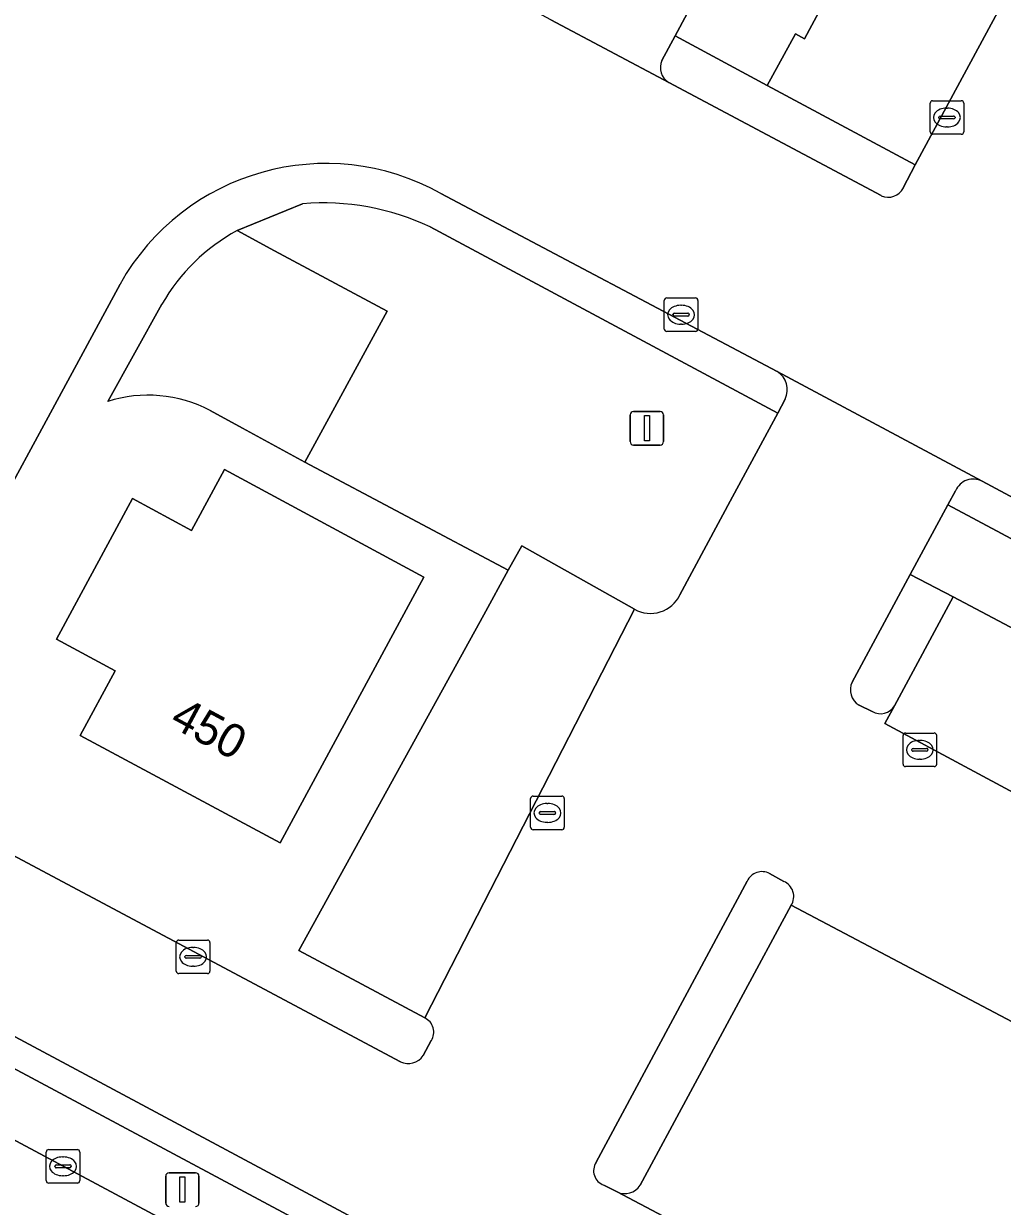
# Model space of a CAD drawing. Extents: x 159489 to 160304, y 383825 to 384531.
# Drawn here: x 159850 to 159879.12, y 383987.85 to 384023.04 of the extents above; entities that cross this region are included whole.
import ezdxf

# ---------------------------------------------------------------- set-up
doc = ezdxf.new("R2010")
doc.units = 0
for name, color, linetype in [('IMGEO_Fietspad_gesloten', 7, 'Continuous'), ('IMGEO_Groenvoorziening', 7, 'Continuous'), ('IMGEO_Haag', 7, 'Continuous'), ('IMGEO_Kolk', 7, 'Continuous'), ('IMGEO_Lichtmast', 7, 'Continuous'), ('IMGEO_Pand', 7, 'Continuous'), ('IMGEO_Pand_nummerreeks', 7, 'Continuous'), ('IMGEO_Parkeervlak_open', 7, 'Continuous'), ('IMGEO_Rijbaan_lokaal_open', 7, 'Continuous'), ('IMGEO_Verkeerseiland_open', 7, 'Continuous'), ('IMGEO_Voetpad_open', 7, 'Continuous')]:
    doc.layers.add(name, color=color, linetype=linetype)

msp = doc.modelspace()

# ---------------------------------------------------------------- linework, layer by layer
at = {"layer": 'IMGEO_Fietspad_gesloten'}
msp.add_lwpolyline([(159914.789, 383954.987), (159829.267, 384000.762), (159827.511, 384001.747), (159820.478, 384006.14), (159815.453, 384008.909), (159814.236, 384009.579), (159812.526, 384010.519), (159810.974, 384011.376), (159809.37, 384007.908)], dxfattribs=at)
at = {"layer": 'IMGEO_Groenvoorziening'}
for points in [[(159874.457, 384024.881), (159874.193, 384025.023), (159893.364, 384060.587), (159890.554, 384062.073), (159888.442, 384058.08), (159889.973, 384057.263), (159884.958, 384047.928), (159883.393, 384048.779), (159869.376, 384022.671), (159872.12, 384021.198), (159872.962, 384022.731), (159873.226, 384022.589)], [(159877.493, 384008.721), (159876.374, 384006.647), (159877.656, 384005.98), (159909.675, 383989.022), (159910.523, 383990.514), (159910.77, 383990.949)]]:
    msp.add_lwpolyline(points, close=True, dxfattribs=at)
for points in [[(159876.169, 384018.149), (159876.524, 384018.834), (159872.12, 384021.198), (159869.376, 384022.671), (159868.985, 384021.943)], [(159869.191, 384021.286), (159875.512, 384017.919)], [(159858.296, 384017.677), (159856.348, 384016.881), (159857.464, 384016.281), (159860.815, 384014.481), (159858.359, 384009.988), (159864.415, 384006.774), (159864.817, 384007.504), (159865.452, 384007.146), (159868.17, 384005.614)], [(159869.523, 384006.042), (159871.091, 384008.959), (159872.432, 384011.452), (159862.09, 384016.991)], [(159833.623, 384000.986), (159833.449, 384000.644), (159914.348, 383957.355), (159917.967, 383963.931), (159926.977, 383980.784), (159923.758, 383982.469), (159924.418, 383983.659), (159923.163, 383984.322), (159922.762, 383983.587), (159923.422, 383983.268), (159922.699, 383982), (159926.104, 383980.377), (159914.162, 383958.38), (159910.232, 383960.503), (159906.502, 383962.5), (159847.363, 383994.162), (159843.388, 383996.29), (159837.377, 383999.508), (159836.092, 384000.196)]]:
    msp.add_lwpolyline(points, dxfattribs=at)
for centre, radius, start, end in [((159869.457, 384021.73), 0.518, 155.7165, 239.1007), ((159875.721, 384018.376), 0.503, 245.4836, 333.1042), ((159858.904, 384010.204), 7.498, 64.8529, 94.649), ((159868.645, 384006.466), 0.975, 240.8553, 334.2526)]:
    msp.add_arc(centre, radius, start, end, dxfattribs=at)
at = {"layer": 'IMGEO_Haag'}
for points in [[(159876.169, 384018.149), (159876.524, 384018.834), (159872.12, 384021.198), (159869.376, 384022.671), (159868.985, 384021.943)], [(159869.191, 384021.286), (159875.512, 384017.919)]]:
    msp.add_lwpolyline(points, dxfattribs=at)
for centre, radius, start, end in [((159869.457, 384021.73), 0.518, 155.7165, 239.1007), ((159875.721, 384018.376), 0.503, 245.4836, 333.1042)]:
    msp.add_arc(centre, radius, start, end, dxfattribs=at)
at = {"layer": 'IMGEO_Kolk'}
for p, q in [((159876.966, 384019.818), (159876.966, 384020.67)), ((159877.041, 384020.744), (159877.893, 384020.744)), ((159877.967, 384020.67), (159877.967, 384019.818)), ((159877.454, 384020.524), (159877.479, 384020.524)), ((159877.225, 384020.238), (159877.225, 384020.25)), ((159877.663, 384020.201), (159877.265, 384020.201)), ((159877.268, 384020.287), (159877.666, 384020.287)), ((159877.477, 384019.964), (159877.452, 384019.964)), ((159877.709, 384020.25), (159877.709, 384020.238)), ((159877.893, 384019.744), (159877.041, 384019.744)), ((159869.057, 384013.951), (159869.057, 384014.803)), ((159869.132, 384014.877), (159869.984, 384014.877)), ((159870.058, 384014.803), (159870.058, 384013.951)), ((159869.316, 384014.371), (159869.316, 384014.383)), ((159869.754, 384014.334), (159869.356, 384014.334)), ((159869.359, 384014.42), (159869.757, 384014.42)), ((159869.545, 384014.657), (159869.57, 384014.657)), ((159869.8, 384014.383), (159869.8, 384014.371)), ((159869.568, 384014.097), (159869.543, 384014.097)), ((159869.984, 384013.877), (159869.132, 384013.877)), ((159876.16, 384001.006), (159876.16, 384001.858)), ((159876.235, 384001.932), (159877.087, 384001.932)), ((159876.648, 384001.712), (159876.673, 384001.712)), ((159877.161, 384001.858), (159877.161, 384001.006)), ((159876.419, 384001.426), (159876.419, 384001.438)), ((159876.857, 384001.389), (159876.459, 384001.389)), ((159876.462, 384001.475), (159876.86, 384001.475)), ((159876.903, 384001.438), (159876.903, 384001.426)), ((159876.671, 384001.152), (159876.646, 384001.152)), ((159877.087, 384000.932), (159876.235, 384000.932)), ((159865.079, 383999.128), (159865.079, 383999.98)), ((159865.154, 384000.054), (159866.006, 384000.054)), ((159866.08, 383999.98), (159866.08, 383999.128)), ((159865.338, 383999.548), (159865.338, 383999.56)), ((159865.381, 383999.597), (159865.779, 383999.597)), ((159865.567, 383999.834), (159865.592, 383999.834)), ((159865.822, 383999.56), (159865.822, 383999.548)), ((159865.776, 383999.511), (159865.378, 383999.511)), ((159865.59, 383999.274), (159865.565, 383999.274)), ((159866.006, 383999.054), (159865.154, 383999.054)), ((159854.537, 383994.847), (159854.537, 383995.699)), ((159854.612, 383995.773), (159855.464, 383995.773)), ((159855.538, 383995.699), (159855.538, 383994.847)), ((159855.025, 383995.553), (159855.05, 383995.553)), ((159854.796, 383995.267), (159854.796, 383995.279)), ((159855.234, 383995.23), (159854.836, 383995.23)), ((159854.839, 383995.316), (159855.237, 383995.316)), ((159855.048, 383994.993), (159855.023, 383994.993)), ((159855.28, 383995.279), (159855.28, 383995.267)), ((159855.464, 383994.773), (159854.612, 383994.773)), ((159850.667, 383988.614), (159850.667, 383989.466)), ((159850.742, 383989.54), (159851.594, 383989.54)), ((159851.668, 383989.466), (159851.668, 383988.614)), ((159850.926, 383989.034), (159850.926, 383989.046)), ((159850.969, 383989.083), (159851.367, 383989.083)), ((159851.155, 383989.32), (159851.18, 383989.32)), ((159851.41, 383989.046), (159851.41, 383989.034)), ((159851.364, 383988.997), (159850.966, 383988.997)), ((159851.178, 383988.76), (159851.153, 383988.76)), ((159851.594, 383988.54), (159850.742, 383988.54))]:
    msp.add_line(p, q, dxfattribs=at)
for points in [[(159876.966, 384019.818), (159876.966, 384020.67)], [(159877.041, 384020.744), (159877.893, 384020.744)], [(159877.967, 384020.67), (159877.967, 384019.818)], [(159877.893, 384019.744), (159877.041, 384019.744)], [(159869.057, 384013.951), (159869.057, 384014.803)], [(159869.132, 384014.877), (159869.984, 384014.877)], [(159870.058, 384014.803), (159870.058, 384013.951)], [(159869.984, 384013.877), (159869.132, 384013.877)], [(159876.16, 384001.006), (159876.16, 384001.858)], [(159876.235, 384001.932), (159877.087, 384001.932)], [(159877.161, 384001.858), (159877.161, 384001.006)], [(159877.087, 384000.932), (159876.235, 384000.932)], [(159865.079, 383999.128), (159865.079, 383999.98)], [(159865.154, 384000.054), (159866.006, 384000.054)], [(159866.08, 383999.98), (159866.08, 383999.128)], [(159866.006, 383999.054), (159865.154, 383999.054)], [(159854.537, 383994.847), (159854.537, 383995.699)], [(159854.612, 383995.773), (159855.464, 383995.773)], [(159855.538, 383995.699), (159855.538, 383994.847)], [(159855.464, 383994.773), (159854.612, 383994.773)], [(159850.667, 383988.614), (159850.667, 383989.466)], [(159850.742, 383989.54), (159851.594, 383989.54)], [(159851.668, 383989.466), (159851.668, 383988.614)], [(159851.594, 383988.54), (159850.742, 383988.54)]]:
    msp.add_lwpolyline(points, dxfattribs=at)
for centre, radius, start, end in [((159877.043, 384020.668), 0.0765, 91.552, 178.448), ((159877.043, 384020.668), 0.0765, 91.552, 178.448), ((159877.891, 384020.668), 0.0765, 1.552, 88.448), ((159877.891, 384020.668), 0.0765, 1.552, 88.448), ((159877.265, 384020.247), 0.0403, 85.8775, 175.7526), ((159877.262, 384020.237), 0.0366, 178.938, 274.7102), ((159877.666, 384020.244), 0.043, 264.8664, 352.4533), ((159877.67, 384020.249), 0.0386, 1.7309, 96.639), ((159877.043, 384019.82), 0.0765, 181.552, 268.448), ((159877.043, 384019.82), 0.0765, 181.552, 268.448), ((159877.891, 384019.82), 0.0765, 271.552, 358.448), ((159877.891, 384019.82), 0.0765, 271.552, 358.448), ((159869.134, 384014.801), 0.0765, 91.552, 178.448), ((159869.134, 384014.801), 0.0765, 91.552, 178.448), ((159869.982, 384014.801), 0.0765, 1.552, 88.448), ((159869.982, 384014.801), 0.0765, 1.552, 88.448), ((159869.356, 384014.38), 0.0403, 85.8775, 175.7526), ((159869.353, 384014.37), 0.0366, 178.938, 274.7102), ((159869.757, 384014.377), 0.043, 264.8664, 352.4533), ((159869.761, 384014.382), 0.0386, 1.7309, 96.639), ((159869.134, 384013.953), 0.0765, 181.552, 268.448), ((159869.134, 384013.953), 0.0765, 181.552, 268.448), ((159869.982, 384013.953), 0.0765, 271.552, 358.448), ((159869.982, 384013.953), 0.0765, 271.552, 358.448), ((159876.237, 384001.856), 0.0765, 91.552, 178.448), ((159876.237, 384001.856), 0.0765, 91.552, 178.448), ((159877.085, 384001.856), 0.0765, 1.552, 88.448), ((159877.085, 384001.856), 0.0765, 1.552, 88.448), ((159876.459, 384001.435), 0.0403, 85.8775, 175.7526), ((159876.456, 384001.425), 0.0366, 178.938, 274.7102), ((159876.86, 384001.432), 0.043, 264.8664, 352.4533), ((159876.864, 384001.437), 0.0386, 1.7309, 96.639), ((159876.237, 384001.008), 0.0765, 181.552, 268.448), ((159876.237, 384001.008), 0.0765, 181.552, 268.448), ((159877.085, 384001.008), 0.0765, 271.552, 358.448), ((159877.085, 384001.008), 0.0765, 271.552, 358.448), ((159865.156, 383999.978), 0.0765, 91.552, 178.448), ((159865.156, 383999.978), 0.0765, 91.552, 178.448), ((159866.004, 383999.978), 0.0765, 1.552, 88.448), ((159866.004, 383999.978), 0.0765, 1.552, 88.448), ((159865.378, 383999.557), 0.0403, 85.8775, 175.7526), ((159865.783, 383999.559), 0.0386, 1.7309, 96.639), ((159865.375, 383999.547), 0.0366, 178.938, 274.7102), ((159865.779, 383999.554), 0.043, 264.8664, 352.4533), ((159865.156, 383999.13), 0.0765, 181.552, 268.448), ((159865.156, 383999.13), 0.0765, 181.552, 268.448), ((159866.004, 383999.13), 0.0765, 271.552, 358.448), ((159866.004, 383999.13), 0.0765, 271.552, 358.448), ((159854.614, 383995.697), 0.0765, 91.552, 178.448), ((159854.614, 383995.697), 0.0765, 91.552, 178.448), ((159855.462, 383995.697), 0.0765, 1.552, 88.448), ((159855.462, 383995.697), 0.0765, 1.552, 88.448), ((159854.836, 383995.276), 0.0403, 85.8775, 175.7526), ((159854.833, 383995.266), 0.0366, 178.938, 274.7102), ((159855.237, 383995.273), 0.043, 264.8664, 352.4533), ((159855.241, 383995.278), 0.0386, 1.7309, 96.639), ((159854.614, 383994.849), 0.0765, 181.552, 268.448), ((159854.614, 383994.849), 0.0765, 181.552, 268.448), ((159855.462, 383994.849), 0.0765, 271.552, 358.448), ((159855.462, 383994.849), 0.0765, 271.552, 358.448), ((159850.744, 383989.464), 0.0765, 91.552, 178.448), ((159850.744, 383989.464), 0.0765, 91.552, 178.448), ((159851.592, 383989.464), 0.0765, 1.552, 88.448), ((159851.592, 383989.464), 0.0765, 1.552, 88.448), ((159850.966, 383989.043), 0.0403, 85.8775, 175.7526), ((159850.963, 383989.033), 0.0366, 178.938, 274.7102), ((159851.367, 383989.04), 0.043, 264.8664, 352.4533), ((159851.371, 383989.045), 0.0386, 1.7309, 96.639), ((159850.744, 383988.616), 0.0765, 181.552, 268.448), ((159850.744, 383988.616), 0.0765, 181.552, 268.448), ((159851.592, 383988.616), 0.0765, 271.552, 358.448), ((159851.592, 383988.616), 0.0765, 271.552, 358.448)]:
    msp.add_arc(centre, radius, start, end, dxfattribs=at)
for centre, major_axis, ratio, start_param, end_param in [((159877.453, 384020.244), (-0.387, 0.002), 0.722429, 4.712389, 7.853982), ((159877.478, 384020.244), (-0.39, 0.002), 0.717154, 1.570796, 4.712389), ((159869.544, 384014.377), (-0.387, 0.002), 0.722429, 4.712389, 7.853982), ((159869.569, 384014.377), (-0.39, 0.002), 0.717154, 1.570796, 4.712389), ((159876.647, 384001.432), (-0.387, 0.002), 0.722429, 4.712389, 7.853982), ((159876.672, 384001.432), (-0.39, 0.002), 0.717154, 1.570796, 4.712389), ((159865.566, 383999.554), (-0.387, 0.002), 0.722429, 4.712389, 7.853982), ((159865.591, 383999.554), (-0.39, 0.002), 0.717154, 1.570796, 4.712389), ((159855.024, 383995.273), (-0.387, 0.002), 0.722429, 4.712389, 7.853982), ((159855.049, 383995.273), (-0.39, 0.002), 0.717154, 1.570796, 4.712389), ((159851.154, 383989.04), (-0.387, 0.002), 0.722429, 4.712389, 7.853982), ((159851.179, 383989.04), (-0.39, 0.002), 0.717154, 1.570796, 4.712389)]:
    msp.add_ellipse(centre, major_axis=major_axis, ratio=ratio, start_param=start_param, end_param=end_param, dxfattribs=at)
at = {"layer": 'IMGEO_Lichtmast'}
for p, q in [((159868.044, 384010.6), (159868.044, 384011.4)), ((159868.044, 384011.4), (159868.044, 384010.6)), ((159868.144, 384011.5), (159868.934, 384011.5)), ((159868.934, 384011.5), (159868.144, 384011.5)), ((159869.034, 384011.4), (159869.034, 384010.6)), ((159869.034, 384010.6), (159869.034, 384011.4)), ((159868.934, 384010.5), (159868.144, 384010.5)), ((159868.144, 384010.5), (159868.934, 384010.5)), ((159854.223, 383987.949), (159854.223, 383988.749)), ((159854.223, 383988.749), (159854.223, 383987.949)), ((159854.323, 383988.849), (159855.113, 383988.849)), ((159855.113, 383988.849), (159854.323, 383988.849)), ((159855.213, 383988.749), (159855.213, 383987.949)), ((159855.213, 383987.949), (159855.213, 383988.749))]:
    msp.add_line(p, q, dxfattribs=at)
for points in [[(159868.464, 384011.375), (159868.614, 384011.375), (159868.614, 384010.625), (159868.464, 384010.625), (159868.464, 384011.375)], [(159854.643, 383988.724), (159854.793, 383988.724), (159854.793, 383987.974), (159854.643, 383987.974), (159854.643, 383988.724)]]:
    msp.add_lwpolyline(points, dxfattribs=at)
for centre, start, end in [((159868.144, 384011.4), 90, 180), ((159868.144, 384011.4), 90, 180), ((159868.934, 384011.4), 0, 90), ((159868.934, 384011.4), 360, 90), ((159868.144, 384010.6), 180, 270), ((159868.144, 384010.6), 180, 270), ((159868.934, 384010.6), 270, 0), ((159868.934, 384010.6), 270, 0), ((159854.323, 383988.749), 90, 180), ((159854.323, 383988.749), 90, 180), ((159855.113, 383988.749), 0, 90), ((159855.113, 383988.749), 360, 90), ((159854.323, 383987.949), 180, 270), ((159854.323, 383987.949), 180, 270), ((159855.113, 383987.949), 270, 0), ((159855.113, 383987.949), 270, 0)]:
    msp.add_arc(centre, 0.1, start, end, dxfattribs=at)
at = {"layer": 'IMGEO_Pand'}
msp.add_lwpolyline([(159861.9, 384006.569), (159855.968, 384009.769), (159854.991, 384007.958), (159853.233, 384008.905), (159850.977, 384004.724), (159852.72, 384003.785), (159851.682, 384001.859), (159857.633, 383998.662)], close=True, dxfattribs=at)
at = {"layer": 'IMGEO_Parkeervlak_open'}
for points in [[(159874.193, 384025.023), (159874.457, 384024.881), (159873.226, 384022.589), (159872.962, 384022.731), (159872.12, 384021.198), (159876.524, 384018.834), (159897.776, 384058.178), (159893.364, 384060.587)], [(159863.687, 384005.452), (159858.186, 383995.461), (159861.931, 383993.454), (159868.17, 384005.614), (159865.452, 384007.146), (159864.817, 384007.504), (159864.415, 384006.774)]]:
    msp.add_lwpolyline(points, close=True, dxfattribs=at)
for points in [[(159877.656, 384005.98), (159875.904, 384002.74), (159875.621, 384002.213), (159919.935, 383978.4), (159921.133, 383980.608), (159914.053, 383984.387)], [(159913.858, 383985.002), (159914.597, 383986.412), (159914.755, 383986.344), (159915.401, 383987.574), (159915.762, 383988.26), (159914.924, 383988.73), (159914.706, 383988.28), (159913.969, 383986.762), (159909.675, 383989.022), (159877.656, 384005.98)], [(159901.88, 383970.695), (159903.894, 383974.382), (159906.443, 383979.069), (159872.835, 383996.806), (159868.337, 383988.475)], [(159867.655, 383988.277), (159902.095, 383970.059)]]:
    msp.add_lwpolyline(points, dxfattribs=at)
msp.add_arc((159867.88, 383988.774), 0.546, 245.5973, 326.7811, dxfattribs=at)
at = {"layer": 'IMGEO_Rijbaan_lokaal_open'}
for points in [[(159875.512, 384017.919), (159869.191, 384021.286), (159865.68, 384023.154), (159860.405, 384026.005), (159861.02, 384027.132), (159860.011, 384027.627), (159880.733, 384067.348), (159880.944, 384067.749)], [(159897.994, 384058.567), (159897.776, 384058.178), (159876.524, 384018.834), (159876.169, 384018.149)], [(159862.412, 384017.983), (159872.417, 384012.684), (159878.518, 384009.42), (159910.32, 383992.364), (159917.028, 383988.832), (159927.536, 383983.189)], [(159847.152, 384004.753), (159852.866, 384015.29)], [(159878.518, 384009.42), (159872.417, 384012.684)], [(159872.655, 384011.867), (159872.432, 384011.452), (159871.091, 384008.959), (159869.523, 384006.042)], [(159874.648, 384003.449), (159876.374, 384006.647), (159877.493, 384008.721), (159877.72, 384009.141)], [(159868.17, 384005.614), (159861.931, 383993.454)], [(159861.206, 383992.151), (159849.659, 383998.303), (159847.363, 383994.162), (159906.502, 383962.5), (159910.232, 383960.503), (159914.616, 383968.515), (159917.813, 383973.681), (159920.243, 383978.197), (159919.935, 383978.4), (159875.621, 384002.213), (159875.904, 384002.74)], [(159875.247, 384002.57), (159874.853, 384002.762)], [(159867.028, 383989.16), (159871.521, 383997.524)], [(159872.192, 383997.754), (159872.613, 383997.519)], [(159872.835, 383996.806), (159906.443, 383979.069)], [(159862.126, 383992.78), (159861.885, 383992.333)], [(159902.664, 383969.778), (159902.095, 383970.059), (159867.655, 383988.277), (159867.258, 383988.481)]]:
    msp.add_lwpolyline(points, dxfattribs=at)
for centre, radius, start, end in [((159858.989, 384011.852), 7.022, 60.8254, 150.683), ((159875.721, 384018.376), 0.503, 245.4836, 333.1042), ((159872.083, 384012.143), 0.635, 334.21, 58.2727), ((159878.25, 384008.905), 0.58, 62.5336, 156.0081), ((159868.645, 384006.466), 0.975, 240.8553, 334.2526), ((159875.118, 384003.215), 0.525, 153.5544, 239.6757), ((159875.489, 384002.991), 0.485, 240.1372, 328.8772), ((159871.968, 383997.313), 0.494, 63.0548, 154.7858), ((159872.415, 383997.066), 0.494, 328.1716, 66.4175), ((159861.73, 383993.031), 0.469, 327.7103, 64.5619), ((159861.44, 383992.637), 0.539, 244.302, 325.7079), ((159867.407, 383988.91), 0.454, 146.5775, 250.8484)]:
    msp.add_arc(centre, radius, start, end, dxfattribs=at)
at = {"layer": 'IMGEO_Verkeerseiland_open'}
for points in [[(159875.904, 384002.74), (159877.656, 384005.98), (159876.374, 384006.647), (159874.648, 384003.449)], [(159874.853, 384002.762), (159875.247, 384002.57)], [(159871.521, 383997.524), (159867.028, 383989.16)], [(159872.613, 383997.519), (159872.192, 383997.754)], [(159868.337, 383988.475), (159872.835, 383996.806)], [(159867.258, 383988.481), (159867.655, 383988.277)]]:
    msp.add_lwpolyline(points, dxfattribs=at)
for centre, radius, start, end in [((159875.118, 384003.215), 0.525, 153.5544, 239.6757), ((159875.489, 384002.991), 0.485, 240.1372, 328.8772), ((159871.968, 383997.313), 0.494, 63.0548, 154.7858), ((159872.415, 383997.066), 0.494, 328.1716, 66.4175), ((159867.407, 383988.91), 0.454, 146.5775, 250.8484), ((159867.88, 383988.774), 0.546, 245.5973, 326.7811)]:
    msp.add_arc(centre, radius, start, end, dxfattribs=at)
at = {"layer": 'IMGEO_Voetpad_open'}
for points in [[(159868.985, 384021.943), (159869.376, 384022.671), (159883.393, 384048.779), (159884.958, 384047.928), (159889.973, 384057.263), (159888.442, 384058.08), (159890.554, 384062.073), (159887.92, 384063.501), (159866.745, 384024.089), (159866.361, 384023.373)], [(159865.68, 384023.154), (159869.191, 384021.286)], [(159872.417, 384012.684), (159862.412, 384017.983)], [(159856.348, 384016.881), (159858.296, 384017.677)], [(159855.543, 384011.528), (159856.506, 384011.001), (159858.359, 384009.988), (159860.815, 384014.481), (159857.464, 384016.281), (159856.348, 384016.881)], [(159862.09, 384016.991), (159872.432, 384011.452), (159872.655, 384011.867)], [(159852.866, 384015.29), (159847.152, 384004.753)], [(159854.109, 384014.693), (159852.497, 384011.797)], [(159852.497, 384011.797), (159854.109, 384014.693)], [(159833.449, 384000.644), (159832.553, 384001.116), (159829.447, 384002.76), (159821.93, 384007.409), (159820.356, 384008.411), (159816.486, 384010.875), (159816.221, 384011.044), (159815.316, 384011.59), (159814.597, 384012.024), (159814.096, 384012.326), (159812.088, 384013.422), (159810.974, 384011.376), (159812.526, 384010.519), (159814.236, 384009.579), (159815.453, 384008.909), (159820.478, 384006.14), (159827.511, 384001.747), (159829.267, 384000.762), (159914.789, 383954.987)], [(159861.931, 383993.454), (159858.186, 383995.461), (159863.687, 384005.452), (159864.415, 384006.774), (159858.359, 384009.988), (159856.506, 384011.001), (159855.543, 384011.528)], [(159877.72, 384009.141), (159877.493, 384008.721), (159910.77, 383990.949), (159914.924, 383988.73), (159915.762, 383988.26), (159916.515, 383987.865), (159917.028, 383988.832), (159910.32, 383992.364), (159878.518, 384009.42)], [(159915.157, 383954.984), (159915.282, 383955.142), (159916.006, 383956.435), (159914.348, 383957.355), (159833.449, 384000.644)], [(159848.803, 383998.781), (159849.659, 383998.303), (159861.206, 383992.151)], [(159861.885, 383992.333), (159862.126, 383992.78)]]:
    msp.add_lwpolyline(points, dxfattribs=at)
msp.add_lwpolyline([(159857.633, 383998.662), (159851.682, 384001.859), (159852.72, 384003.785), (159850.977, 384004.724), (159853.233, 384008.905), (159854.991, 384007.958), (159855.968, 384009.769), (159861.9, 384006.569)], close=True, dxfattribs=at)
for centre, radius, start, end in [((159869.457, 384021.73), 0.518, 155.7165, 239.1007), ((159858.989, 384011.852), 7.022, 60.8254, 150.683), ((159858.904, 384010.204), 7.498, 64.8529, 94.649), ((159859.13, 384011.795), 5.797, 118.6745, 150.0054), ((159859.13, 384011.795), 5.797, 118.6745, 150.0054), ((159872.083, 384012.143), 0.635, 334.21, 58.2727), ((159853.698, 384008.019), 3.964, 62.2681, 107.6383), ((159853.698, 384008.019), 3.964, 62.2681, 107.6383), ((159878.25, 384008.905), 0.58, 62.5336, 156.0081), ((159861.73, 383993.031), 0.469, 327.7103, 64.5619), ((159861.44, 383992.637), 0.539, 244.302, 325.7079)]:
    msp.add_arc(centre, radius, start, end, dxfattribs=at)

# ---------------------------------------------------------------- texts
at = {"layer": 'IMGEO_Pand_nummerreeks'}
msp.add_text('450', height=1, rotation=331.7532, dxfattribs=at).set_placement((159854.299, 384002.156))

doc.saveas('drawing.dxf')
